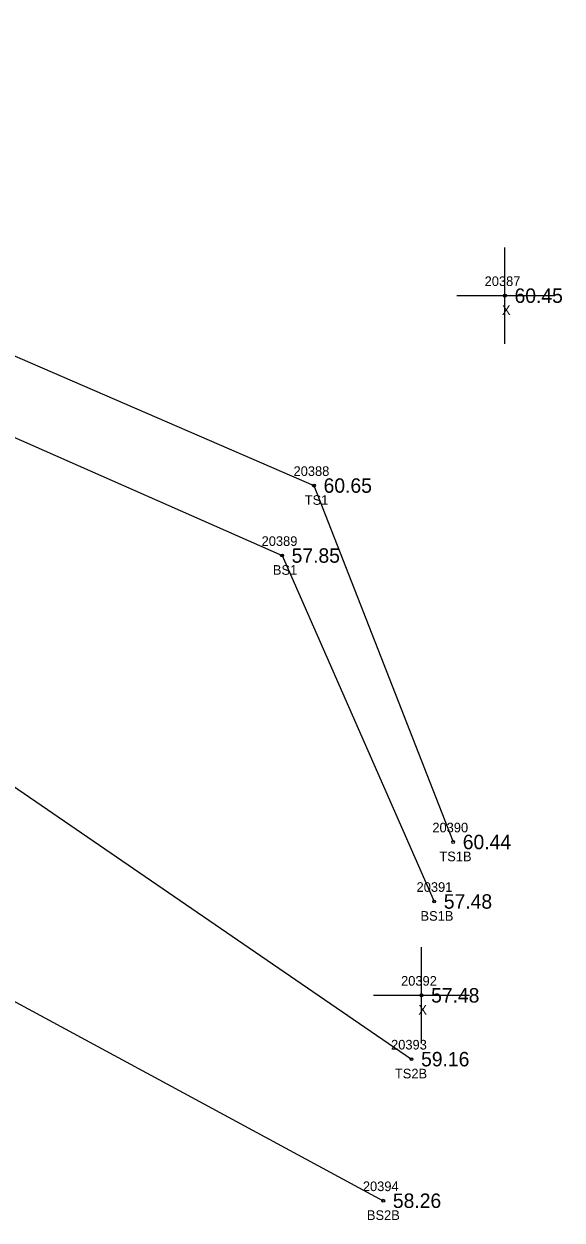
# Model space of a CAD drawing. Extents: x 2420351 to 2422725, y 845330 to 846558.
# Drawn here: x 2420968.2 to 2421024.1, y 845522.4 to 845646.7 of the extents above; entities that cross this region are included whole.
import ezdxf

# ---------------------------------------------------------------- set-up
doc = ezdxf.new("R2010")
doc.units = 0
for name, color, linetype in [('RD_DTM_BkLn2', 7, 'Continuous'), ('RD_DTM_BkLn_txCode', 7, 'Continuous'), ('RD_EX_Misc', 7, 'Continuous'), ('RD_EX_Misc_txCode', 7, 'Continuous'), ('RD_EX_TX_Misc_ELEV', 7, 'Continuous'), ('RD_SMD_Locator', 7, 'Continuous')]:
    doc.layers.add(name, color=color, linetype=linetype)

msp = doc.modelspace()

# ---------------------------------------------------------------- linework, layer by layer
at = {"layer": 'RD_DTM_BkLn2'}
for points in [[(2420391.68, 845656.64), (2420445.21, 845668.26), (2420499.47, 845673.15), (2420555.79, 845685.67), (2420611.25, 845685.1), (2420638.03, 845688.28), (2420664.95, 845679.28), (2420684.17, 845674.37), (2420751.52, 845659.06), (2420788.44, 845663), (2420892.57, 845636.64), (2420995.04, 845591.46), (2421010.85, 845555.52)], [(2420638.03, 845688.28), (2420664.65, 845684.42), (2420684.3, 845682.54), (2420748.92, 845680.65), (2420790.66, 845674.79), (2420895.81, 845643.13), (2420998.36, 845598.73), (2421012.82, 845561.7)], [(2420554.48, 845663.6), (2420612.71, 845664.41), (2420685.79, 845655.34), (2420750.14, 845647.33), (2420785.66, 845648.26), (2420885.87, 845623.22), (2421008.49, 845539.14)], [(2420554.18, 845658.61), (2420613.14, 845658.42), (2420684.62, 845647.43), (2420749.31, 845640.38), (2420783.25, 845635.49), (2420872.47, 845596.38), (2421005.56, 845524.43)]]:
    msp.add_lwpolyline(points, dxfattribs=at)
at = {"layer": 'RD_EX_Misc'}
for p, q in [((2421018.2, 845613.46), (2421018.2, 845623.46)), ((2421013.2, 845618.46), (2421023.2, 845618.46)), ((2421009.53, 845540.77), (2421009.53, 845550.77)), ((2421004.53, 845545.77), (2421014.53, 845545.77))]:
    msp.add_line(p, q, dxfattribs=at)
at = {"layer": 'RD_SMD_Locator'}
for centre in [(2421018.2, 845618.46), (2420998.36, 845598.73), (2420995.04, 845591.46), (2421012.82, 845561.7), (2421010.85, 845555.52), (2421009.53, 845545.77), (2421008.49, 845539.14), (2421005.56, 845524.43)]:
    msp.add_circle(centre, 0.15, dxfattribs=at)

# ---------------------------------------------------------------- texts
at = {"layer": 'RD_DTM_BkLn_txCode'}
for s, p in [('20388', (2420996.24, 845599.73)), ('TS1', (2420997.4, 845596.73)), ('20389', (2420992.92, 845592.46)), ('BS1', (2420994.09, 845589.46)), ('20390', (2421010.66, 845562.7)), ('TS1B', (2421011.39, 845559.7)), ('20391', (2421009.02, 845556.52)), ('BS1B', (2421009.43, 845553.52)), ('20393', (2421006.37, 845540.14)), ('TS2B', (2421006.77, 845537.14)), ('20394', (2421003.44, 845525.43)), ('BS2B', (2421003.86, 845522.43))]:
    msp.add_text(s, height=1, dxfattribs=at).set_placement(p)
at = {"layer": 'RD_EX_Misc_txCode'}
for s, p in [('20387', (2421016.09, 845619.46)), ('X', (2421017.89, 845616.46)), ('20392', (2421007.41, 845546.77)), ('X', (2421009.21, 845543.77))]:
    msp.add_text(s, height=1, dxfattribs=at).set_placement(p)
at = {"layer": 'RD_EX_TX_Misc_ELEV'}
for s, p in [('60.45', (2421019.2, 845617.71)), ('60.65', (2420999.36, 845597.98)), ('57.85', (2420996.04, 845590.71)), ('60.44', (2421013.82, 845560.95)), ('57.48', (2421011.85, 845554.77)), ('57.48', (2421010.53, 845545.02)), ('59.16', (2421009.49, 845538.39)), ('58.26', (2421006.56, 845523.68))]:
    msp.add_text(s, height=1.5, dxfattribs=at).set_placement(p)

doc.saveas('drawing.dxf')
